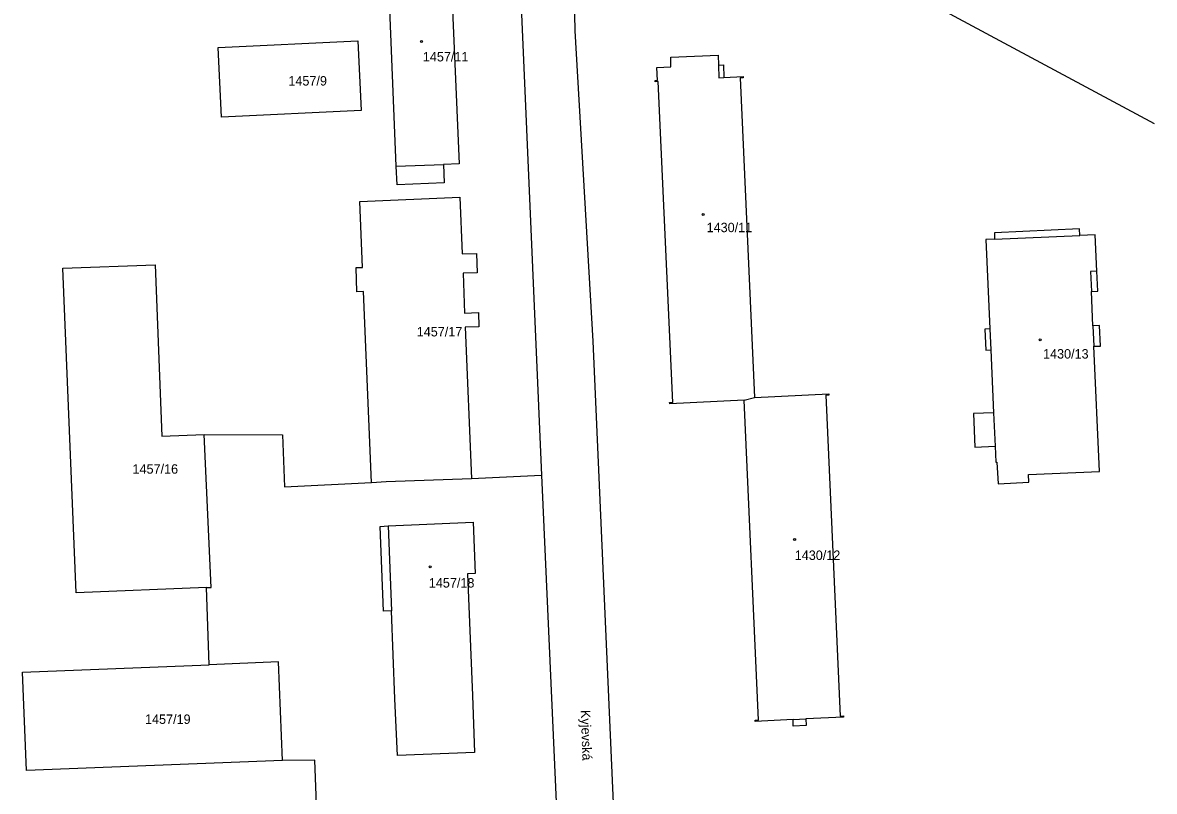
# Model space of a CAD drawing. Extents: x -736397 to -735924, y -1118983 to -1118245.
# Drawn here: x -736132.1 to -735928, y -1118593.4 to -1118454.8 of the extents above; entities that cross this region are included whole.
import ezdxf

# ---------------------------------------------------------------- set-up
doc = ezdxf.new("R2010")
doc.units = 0
for name, color, linetype in [('Vrstva 1', 7, 'Continuous'), ('Vrstva 15', 7, 'Continuous'), ('Vrstva 18', 7, 'Continuous'), ('Vrstva 19', 7, 'Continuous'), ('Vrstva 25', 7, 'Continuous'), ('Vrstva 4', 7, 'Continuous')]:
    doc.layers.add(name, color=color, linetype=linetype)

msp = doc.modelspace()

# ---------------------------------------------------------------- linework, layer by layer
at = {"layer": 'Vrstva 1'}
for p, q in [((-735939.11, -1118509.48), (-735939.39, -1118503.3)), ((-735957.54, -1118513.83), (-735957.03, -1118525.14)), ((-736002, -1118522.91), (-736000.11, -1118522.38)), ((-736051.17, -1118536.98), (-736038.55, -1118536.42)), ((-736038.55, -1118536.42), (-736034.02, -1118635.86)), ((-736098.42, -1118570.58), (-736098.93, -1118556.67))]:
    msp.add_line(p, q, dxfattribs=at)
for points in [[(-736052.29, -1118402.89), (-736052.52, -1118407.59), (-736048.25, -1118408.23), (-736045.95, -1118409.28), (-736043.72, -1118413.88), (-736042.87, -1118436.57), (-736038.55, -1118536.42)], [(-735928.04, -1118473.03), (-736016.57, -1118425.44), (-736008.14, -1118409.65)], [(-736022.3, -1118670.45), (-736022.74, -1118659.75), (-736029.23, -1118512.27), (-736032.47, -1118456.28), (-736033.2, -1118421.05)], [(-736064.7, -1118480.68), (-736066.37, -1118440.43), (-736061.43, -1118440.24)], [(-736059.79, -1118440.18), (-736055.12, -1118440), (-736053.39, -1118480.25), (-736056.21, -1118480.36)], [(-736096.82, -1118459.28), (-736071.66, -1118458.08), (-736071.05, -1118470.65), (-736096.23, -1118471.87), (-736096.82, -1118459.28)], [(-736002, -1118522.91), (-736015.42, -1118523.52), (-736015.43, -1118523.32), (-736014.85, -1118523.29), (-736017.47, -1118465.43), (-736018.05, -1118465.46), (-736018.06, -1118465.26), (-736017.64, -1118465.24), (-736017.75, -1118462.9), (-736015.23, -1118462.78), (-736015.23, -1118461.05), (-736006.65, -1118460.65), (-736006.6, -1118462.46)], [(-736006.6, -1118462.46), (-736005.71, -1118462.4), (-736005.66, -1118464.7)], [(-736005.66, -1118464.7), (-736002.15, -1118464.54), (-736002.14, -1118464.74), (-736002.72, -1118464.77), (-736000.11, -1118522.38)], [(-736056.21, -1118480.36), (-736056.1, -1118483.69), (-736064.56, -1118484.05), (-736064.7, -1118480.68)], [(-736069.2, -1118537.73), (-736070.61, -1118503.31), (-736071.81, -1118503.35), (-736071.94, -1118498.97), (-736070.79, -1118498.93), (-736071.28, -1118487.05), (-736053.23, -1118486.3), (-736052.82, -1118496.5), (-736050.26, -1118496.42), (-736050.14, -1118499.9), (-736052.67, -1118500), (-736052.38, -1118507.18), (-736049.9, -1118507.08), (-736049.84, -1118509.64), (-736052.28, -1118509.74), (-736051.17, -1118536.98)], [(-735941.45, -1118493.17), (-735941.52, -1118492.01), (-735956.88, -1118492.72), (-735956.83, -1118493.87)], [(-735956.83, -1118493.87), (-735958.43, -1118493.94), (-735957.71, -1118510.02)], [(-735938.39, -1118499.61), (-735938.69, -1118493.05), (-735941.45, -1118493.17)], [(-736098.93, -1118556.67), (-736122.41, -1118557.62), (-736124.81, -1118499.1), (-736108.2, -1118498.49), (-736106.95, -1118529.35), (-736099.32, -1118529.05)], [(-735939.39, -1118503.3), (-735938.22, -1118503.25), (-735938.39, -1118499.61)], [(-735957.71, -1118510.02), (-735958.61, -1118510.07), (-735958.44, -1118513.87), (-735957.54, -1118513.83)], [(-735938.95, -1118513.17), (-735937.73, -1118513.12), (-735937.9, -1118509.43), (-735939.11, -1118509.48)], [(-735956.76, -1118531.18), (-735956.63, -1118534.07), (-735956.44, -1118534.04), (-735956.19, -1118537.94), (-735950.65, -1118537.68), (-735950.75, -1118536.27), (-735937.94, -1118535.76), (-735938.95, -1118513.17)], [(-736000.11, -1118522.38), (-735986.71, -1118521.77), (-735986.7, -1118521.97), (-735987.28, -1118522), (-735984.67, -1118579.86), (-735984.09, -1118579.83), (-735984.08, -1118580.03), (-735990.88, -1118580.36)], [(-735993.18, -1118580.47), (-736000, -1118580.8), (-736000.01, -1118580.6), (-735999.43, -1118580.57), (-736002, -1118522.91)], [(-735957.03, -1118525.14), (-735960.63, -1118525.28), (-735960.42, -1118531.33), (-735956.76, -1118531.18)], [(-736098.93, -1118556.67), (-736098.08, -1118556.64), (-736099.32, -1118529.05)], [(-736099.32, -1118529.05), (-736085.22, -1118529.13), (-736084.83, -1118538.51), (-736069.2, -1118537.73)], [(-736069.2, -1118537.73), (-736066.55, -1118537.53), (-736051.17, -1118536.98)], [(-736066.2, -1118545.56), (-736050.85, -1118544.88), (-736050.47, -1118554.14), (-736051.88, -1118554.2), (-736050.98, -1118576.13), (-736050.59, -1118586.44), (-736064.48, -1118586.97), (-736064.94, -1118576.72), (-736065.59, -1118560.88)], [(-736065.59, -1118560.88), (-736067.03, -1118560.94), (-736067.64, -1118545.65), (-736066.2, -1118545.56)], [(-736085.22, -1118587.86), (-736131.36, -1118589.69), (-736132.07, -1118571.94), (-736098.42, -1118570.58)], [(-736085.22, -1118587.86), (-736085.96, -1118570.07), (-736098.42, -1118570.58)], [(-735990.88, -1118580.36), (-735990.84, -1118581.57), (-735993.13, -1118581.66), (-735993.18, -1118580.47)], [(-736059.09, -1118636.12), (-736058.84, -1118638.43), (-736077.48, -1118638.73), (-736079.39, -1118587.8), (-736085.22, -1118587.86)]]:
    msp.add_lwpolyline(points, dxfattribs=at)
at = {"layer": 'Vrstva 25'}
for centre in [(-736060.18, -1118458.2), (-736009.38, -1118489.39), (-735948.62, -1118511.98), (-735992.89, -1118548.03), (-736058.61, -1118552.96)]:
    msp.add_ellipse(centre, major_axis=(0.18, 0), ratio=0.984808, dxfattribs=at)
at = {"layer": 'Vrstva 4'}
for p, q in [((-736064.7, -1118480.68), (-736056.21, -1118480.36)), ((-735956.83, -1118493.87), (-735941.45, -1118493.17)), ((-735957.71, -1118510.02), (-735957.54, -1118513.83)), ((-735939.11, -1118509.48), (-735938.95, -1118513.17)), ((-735957.03, -1118525.14), (-735956.76, -1118531.18)), ((-736066.2, -1118545.56), (-736065.59, -1118560.88)), ((-735993.18, -1118580.47), (-735990.88, -1118580.36))]:
    msp.add_line(p, q, dxfattribs=at)
for points in [[(-736006.6, -1118462.46), (-736006.54, -1118464.74), (-736005.66, -1118464.7)], [(-735938.39, -1118499.61), (-735939.55, -1118499.66), (-735939.39, -1118503.3)]]:
    msp.add_lwpolyline(points, dxfattribs=at)

# ---------------------------------------------------------------- texts
at = {"layer": 'Vrstva 15'}
msp.add_text('Kyjevská', height=1.7, rotation=271.9897, dxfattribs=at).set_placement((-736031.45, -1118578.78))
at = {"layer": 'Vrstva 18'}
for s, p in [('1457/9', (-736084.16, -1118466.15)), ('1457/17', (-736061.02, -1118511.39)), ('1457/16', (-736112.26, -1118536.14)), ('1457/19', (-736110.01, -1118581.26))]:
    msp.add_text(s, height=1.7, dxfattribs=at).set_placement(p)
at = {"layer": 'Vrstva 19'}
for s, p in [('1457/11', (-736059.92, -1118461.8)), ('1430/11', (-736008.76, -1118492.59)), ('1430/13', (-735948.11, -1118515.38)), ('1430/12', (-735992.87, -1118551.69)), ('1457/18', (-736058.84, -1118556.67))]:
    msp.add_text(s, height=1.7, dxfattribs=at).set_placement(p)

doc.saveas('drawing.dxf')
